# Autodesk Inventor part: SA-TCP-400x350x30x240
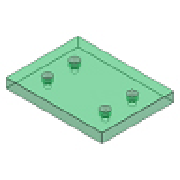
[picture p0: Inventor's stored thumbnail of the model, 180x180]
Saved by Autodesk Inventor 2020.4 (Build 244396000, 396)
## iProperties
Created: 2019-01
Part Number: SA-TCP-400x350x30x240
Material: S 55 C
Description: Top Clamping Plate
Document SubType Name: Modeling
Designer: mel
Standard Revision: 1
Manufacturer: FUTABA
Language: fr-FR
Size Designation: 400x350x30x240
Categories: <MemberInstance><Categories><Category DisplayName="Moule" InternalName="349578f2-f4d4-4954-8c09-8e99297a61c0" Mnemonic="MOLD"><Category DisplayName="Plaque de m
Density: 7.85 g/cm^3
Appearance: Clear - Green 1
IsCustomPart: 1
Author: mel
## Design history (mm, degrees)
sketch "Sketch1"
  geometry: L1 (-175, 200)-(175, 200); L2 (175, 200)-(175, -200); L3 (175, -200)-(-175, -200); L4 (-175, -200)-(-175, 200); 3 further points
  constraints: 8 end point, 2 midpoint, 2 parallel, 1 horizontal, 1 horizontal alignment, 1 perpendicular, 1 vertical alignment
  dimensions: "d72" = 350 distance between parallel lines of L2 L4 (= W_); "d73" = 400 distance between parallel lines of L3 L1 (= L)
extrude "Extrusion1" new body sketch "Sketch1" distance "d20" = 30 (= H_); taper "d30" = 0 deg
sketch "Sketch2"
  geometry: 2 further points
  dimensions: "d53" = 120 horizontal distance of point (0, 0) point (-120, 119) (= 0.5 x S1_W); "d54" = 119 vertical distance of point (0, 0) point (-120, 119) (= 0.5 x S1_L)
hole "Hole1" sketch "Sketch2" at (-120, 119) diameter "d55" = 16 (= S1_d1); stored, may be unused: countersink angle "d59" = 90 deg, drill point angle "d61" = 0 deg; dims "d56" = 6, "d57" = 24 (= S1_d2), "d58" = 15 (= S1_k), "d60" = 30 (= H_)
pattern_linear "Rectangular Pattern1" dims "d64" = 119 (computed from S1_L, Ns), "d67" = 240 (computed from S1_W, Nw)
chamfer "Chamfer1" distance "d68" = 0.5; stored, may be unused: second distance "d69" = 2, angle "d71" = 45 deg
feature "Sculpter1"
feature "Sculpter2"
body "Solid1"
feature "Surface1"
body "Srf1"
feature "Surface2"
body "Srf2"
other parameters: "L" = 400 [user parameter; used in 1 equation term], "W_" = 350 [user parameter; used in 1 equation term], "H_" = 30 [user parameter; used in 2 equation terms], "S1_d1" = 16 [user parameter; used in 1 equation term], "S1_d2" = 24 [user parameter; used in 1 equation term], "S1_k" = 15 [user parameter; used in 1 equation term], "S1_L" = 238 [user parameter; used in 2 equation terms]
